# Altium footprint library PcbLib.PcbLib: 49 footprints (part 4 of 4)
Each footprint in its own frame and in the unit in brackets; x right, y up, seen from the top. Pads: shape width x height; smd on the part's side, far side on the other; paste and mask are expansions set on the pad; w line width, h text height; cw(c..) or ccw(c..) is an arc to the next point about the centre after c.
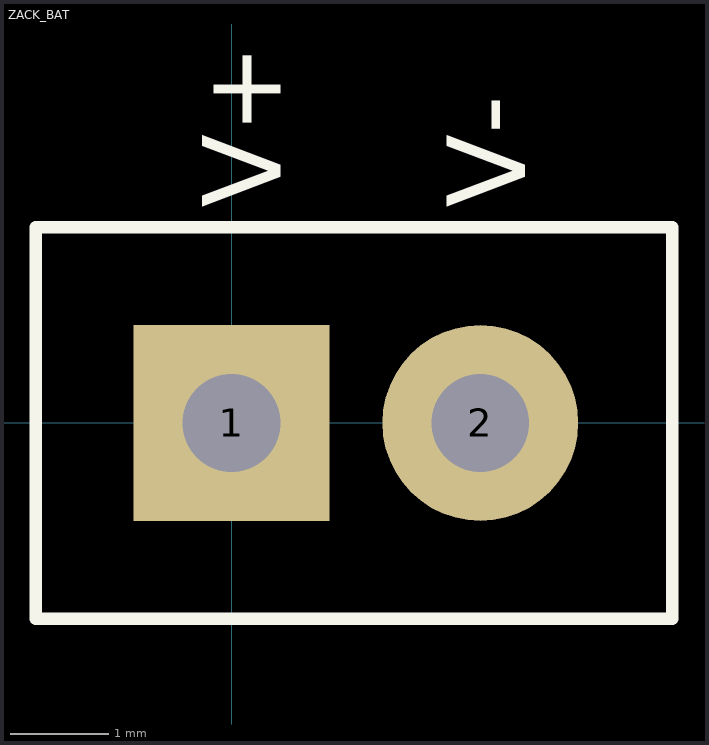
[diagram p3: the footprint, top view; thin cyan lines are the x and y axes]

## ZACK_BAT [mm] "HEADER, SINGLE, DISTANCE = 100mil"
pads (2):
  rect 2x2 hole 1: 1(0,0)
  round 2 hole 1: 2(2.54,0)
Top Overlay:
  lines w0.127: -2,-2 4.5,-2 4.5,2 -2,2 -2,-2
  text "V-" at 3,2.2 h0.8
  text "V+" at 0.5,2.2 h0.8
3D body "User Library-Header1x2.STEP": height 8.17, standoff -2.81, extent -1.34,-1.3 3.74,1.24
